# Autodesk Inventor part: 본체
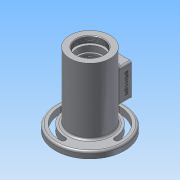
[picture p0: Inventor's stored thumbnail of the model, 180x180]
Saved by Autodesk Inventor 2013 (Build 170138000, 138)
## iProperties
Created: 2017-05
Part Number: 본체
Material: 알루미늄 6061
Document SubType Name: Modeling
Designer: Administrator
Density: 2.71 g/cm^3
Mass: 676.471 g
Surface Area: 616.844 cm^2
Volume: 249.62 cm^3
Author: Administrator
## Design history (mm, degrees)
sketch "스케치1"
  geometry: C1 r 53 at (0, 0); C2 r 31 at (0, 0); 1 further point
  constraints: 2 centre point, 2 coincident
  dimensions: "d0" = 106 diameter of C1; "d1" = 62 diameter of C2
extrude "돌출1" new body sketch "스케치1" distance "d2" = 10; taper "d3" = 0 deg
extrude "돌출2" join sketch "스케치1" distance "d4" = 3; taper "d5" = 0 deg
sketch "스케치2"
  geometry: C1 r 53 at (0, 0) reference; C2 r 31 at (0, 0)
  constraints: 1 centre point, 1 coincident
  dimensions: "d6" = 62 diameter of C2
extrude "돌출3" join sketch "스케치2" distance "d7" = 102; taper "d8" = 0 deg
sketch "스케치3"
  geometry: C1 r 22 at (0, 0); 1 further point
  constraints: 1 centre point, 1 coincident
  dimensions: "d9" = 44 diameter of C1
node "작업 평면1"
sketch "스케치4"
  geometry: C1 r 16 at (0, 0); 1 further point
  constraints: 1 centre point, 1 coincident
  dimensions: "d11" = 32 diameter of C1
feature "로프트1" sketch "스케치4" dims "d12" = 0, "d13" = 90 deg, "d14" = 0, "d15" = 90 deg
hole "구멍1" diameter "d18" = 20; stored, may be unused: countersink angle "d22" = 90 deg, drill point angle "d24" = 0 deg; dims "d19" = 6, "d20" = 25, "d21" = 7.3, "d23" = 8, "d73" = 10, "d74" = 10
hole "구멍2" diameter "d27" = 42; stored, may be unused: countersink angle "d31" = 90 deg, drill point angle "d33" = 0 deg; dims "d25" = 10, "d26" = 10, "d28" = 6, "d29" = 25, "d30" = 7.3, "d32" = 9
sketch "스케치5"
  geometry: L1 (-21, 112)-(21, 112) reference; L2 (22, -3)-(-22, -3) reference; L3 (0, 112)-(0, -3); L4 (21, 103)-(-21, 103) reference; L5 (0, 103)-(24, 103); L6 (24, 103)-(24, 100); L7 (24, 100)-(0, 100); L8 (0, 100)-(0, 103); 1 further point
  constraints: 10 end point, 3 midpoint, 2 parallel, 1 horizontal, 1 perpendicular
  dimensions: "d37" = 3 distance of L5.end L6.end; "d39" = 24 distance of L6.end L7.end
revolve "회전1" sketch "스케치5" stored, may be unused: angle "d40" = 90 deg
hole "구멍3" diameter "d43" = 35; stored, may be unused: countersink angle "d47" = 90 deg, drill point angle "d49" = 0 deg; dims "d44" = 6, "d45" = 40, "d46" = 9, "d48" = 74, "d123" = 10, "d124" = 10
sketch "스케치6"
  geometry: L1 (-21, 112)-(21, 112) reference; L2 (22, -3)-(-22, -3) reference; L3 (0, 112)-(0, -3); L4 (0, 87.75)-(18.5, 87.75); L5 (18.5, 87.75)-(18.5, 86); L6 (18.5, 86)-(0, 86); L7 (0, 87.75)-(0, 86); 1 further point
  constraints: 10 end point, 3 perpendicular, 2 midpoint, 2 point on line, 1 parallel
  dimensions: "d52" = 1.75 distance of L4.end L5.end; "d54" = 18.5 distance of L5.end L6.end; "d55" = 26 distance between parallel lines of L1 L6
revolve "회전2" sketch "스케치6" stored, may be unused: angle "d56" = 90 deg
sketch "스케치7"
  geometry: L1 (-21, 112)-(21, 112) reference; L2 (22, -3)-(-22, -3) reference; L3 (0, 112)-(0, -3); L4 (0, 75)-(26, 75); L5 (26, 75)-(26, 37); L6 (26, 37)-(0, 37); L7 (0, 75)-(0, 37); 1 further point
  constraints: 10 end point, 3 perpendicular, 2 midpoint, 2 point on line, 1 collinear
  dimensions: "d57" = 38 distance of L4.end L5.end; "d59" = 26 distance of L5.end L6.end; "d60" = 37 distance between parallel lines of L1 L4
revolve "회전3" sketch "스케치7" stored, may be unused: angle "d61" = 90 deg
hole "구멍4" diameter "d66" = 33; stored, may be unused: countersink angle "d70" = 90 deg, drill point angle "d72" = 0 deg; dims "d64" = 10, "d65" = 10, "d67" = 6, "d68" = 4, "d69" = 2, "d71" = 5
sketch "스케치8"
  geometry: 1 further point
fillet "모깎기1" dims "d112" = 3, "d113" = 0.3
node "작업 평면2"
sketch "스케치10"
  geometry: L1 (20, 81)-(-20, 81); L2 (-20, 81)-(-20, 31); L3 (-20, 31)-(20, 31); L4 (20, 31)-(20, 81); L5 (31, 112)-(-31, 112) reference; L6 (11, 72)-(-11, 72); L7 (-11, 72)-(-11, 40); L8 (-11, 40)-(11, 40); L9 (11, 40)-(11, 72); 2 further points
  constraints: 16 end point, 4 parallel, 2 perpendicular, 1 horizontal, 1 midpoint, 1 vertical alignment, 3 other
  dimensions: "d76" = 50 distance of L3.end L1.start; "d80" = 40 distance of L1.start L1.end; "d81" = 31 distance between parallel lines of L1 L5; "d82" = 32 distance of L6.end L7.end
extrude "돌출4" join sketch "스케치10" stored distance "d83" = 10; taper "d84" = 0 deg
extrude "돌출5" cut sketch "스케치10" distance "d85" = 40; taper "d86" = 0 deg
sketch "스케치11"
  geometry: L1 (11, -40)-(11, -72) reference; L2 (-11, -72)-(-11, -40) reference; L3 (-20, -81)-(20, -81) reference; L4 (20, -31)-(-20, -31) reference; L5 (-11, -56)-(11, -56); L6 (0, -81)-(0, -31); 5 further points
  constraints: 4 end point, 4 midpoint, 2 horizontal alignment, 2 vertical alignment
  dimensions: "d87" = 41 distance of point (-15.5, -35.5) point (-15.5, -76.5); "d89" = 20.5 distance from line of point (-15.5, -76.5) L5; "d90" = 31 distance of point (15.5, -76.5) point (-15.5, -76.5); "d91" = 15.5 distance from line of L6 point (15.5, -76.5)
hole "구멍5" sketch "스케치11" at (-15.5, -76.5), (-15.5, -35.5), (15.5, -35.5), (15.5, -76.5) diameter "d92" = 2.459; stored, may be unused: countersink angle "d96" = 90 deg, drill point angle "d98" = 118 deg; dims "d93" = 6, "d94" = 4, "d95" = 2, "d97" = 8
feature "스레드1" dims "d99" = 10, "d100" = 0
sketch "스케치12"
  geometry: L1 (0, 53)-(0, 0); L2 (0, 0)-(-53, 0); C1 r 31 at (0, 0) reference; A1 r 53 centre (0, 0) between (0, 53) and (-53, 0) reference; A2 r 45.5 centre (0, 0) between (0, 45.5) and (-45.5, 0); A3 r 37.5 centre (0, 0) between (0, 37.5) and (-37.5, 0); A4 r 4 centre (0, 41.5) between (0, 37.5) and (0, 45.5); A5 r 4 centre (-41.5, 0) between (-45.5, 0) and (-37.5, 0); A6 r 45.5 centre (0, 0) between (0, -45.5) and (45.5, 0); A7 r 37.5 centre (0, 0) between (0, -37.5) and (37.5, 0); A8 r 4 centre (41.5, 0) between (45.5, 0) and (37.5, 0); A9 r 4 centre (0, -41.5) between (0, -37.5) and (0, -45.5)
  constraints: 18 point on circle, 8 centre point, 8 tangent, 4 end point, 2 coincident, 2 horizontal alignment, 2 point on line, 1 perpendicular, 1 vertical, 1 vertical alignment
  dimensions: "d101" = 45.5 radius of A2; "d104" = 37.5 radius of A3; "d105" = 45.5 radius of A6; "d106" = 37.5 radius of A7
extrude "돌출6" cut sketch "스케치12" distance "d107" = 13; taper "d108" = 0 deg
chamfer "모따기1" distance "d109" = 1; stored, may be unused: second distance "d110" = 2, angle "d111" = 45 deg
fillet "모깎기2" dims "d114" = 3
sketch "스케치13"
  geometry: L1 (0, 0)-(44, 0) reference; L2 (-34, -13)-(-34, -75) reference; 2 further points
  constraints: 1 other
  dimensions: "d116" = 56 distance from line of L2 point (22, -8); "d117" = 8 distance from line of L1 point (22, -8)
feature "엠보싱1" sketch "스케치13" dims "d1" = 62, "d12" = 0, "d13" = 90 deg, "d14" = 0, "d15" = 90 deg, "d118" = 0.5, "d119" = 0
chamfer "모따기2" distance "d120" = 0.7; stored, may be unused: second distance "d121" = 2, angle "d122" = 30 deg
chamfer "모따기3" distance "d125" = 1; stored, may be unused: second distance "d126" = 2, angle "d127" = 45 deg
node "솔리드1"
other parameters: "d10" = -11, "d75" = 44
